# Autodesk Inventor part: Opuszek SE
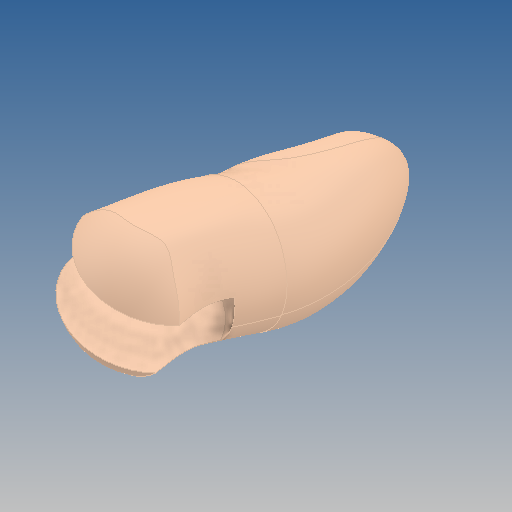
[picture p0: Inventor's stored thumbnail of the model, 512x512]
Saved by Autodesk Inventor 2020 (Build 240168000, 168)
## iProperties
Created: 2019-10
Part Number: Opuszek SE
Material: GFRP
Document SubType Name: Modeling
Designer: yello
Density: 1.75 g/cm^3
Appearance: Default
Author: yello
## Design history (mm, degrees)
feature "Opuszek SE"
body "Solid1"
